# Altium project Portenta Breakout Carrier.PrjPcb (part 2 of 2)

## Sheet HDConn_MALE.SchDoc: Portenta Breakout Carrier
size A3; Author: S. Navaretti; DocumentNumber: ASX00031; Revision: V1.3; SheetNumber: 6; SheetTotal: 6; RevAuthor: Silvio Navaretti
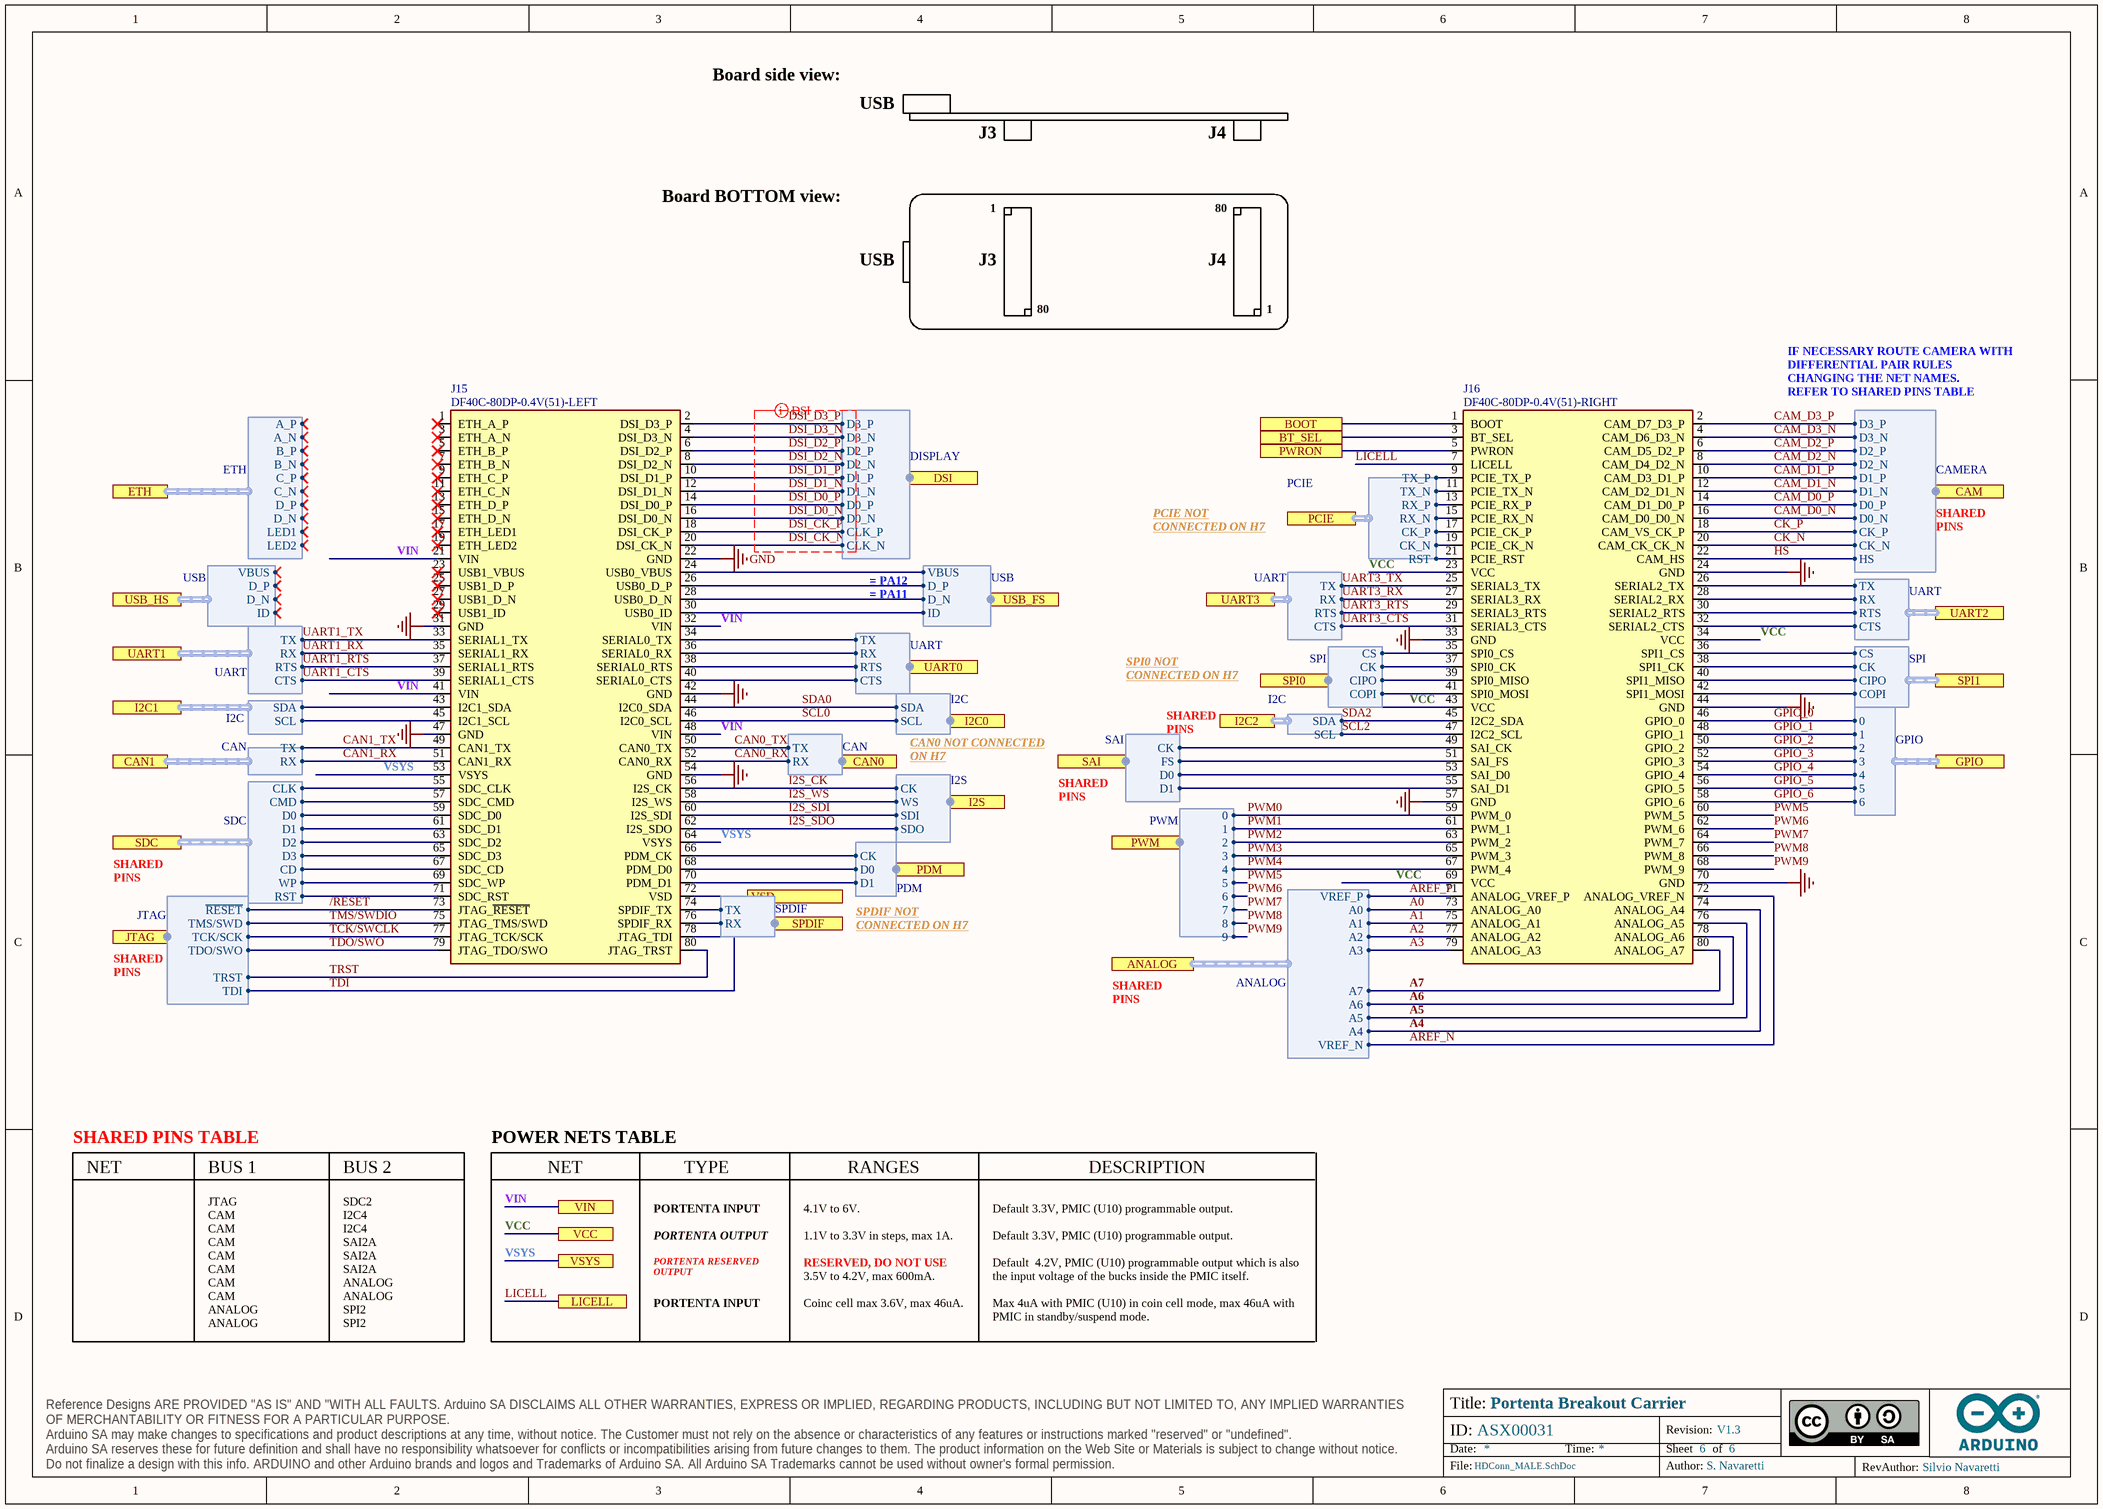
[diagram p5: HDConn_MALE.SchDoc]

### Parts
J15  DF40C-80DP-0.4V(51)-LEFT  [DF40C-80DP-0.4V(51)-Footprint-1]
J16  DF40C-80DP-0.4V(51)-RIGHT  [DF40C-80DP-0.4V(51)-Footprint-1]

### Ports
ANALOG (harness ANALOG), BOOT, BT_SEL, CAM (harness CAMERA), CAN0 (harness CAN), CAN1 (harness CAN), DSI (harness DISPLAY), ETH (harness ETH), GPIO (harness GPIO), I2C0 (harness I2C), I2C1 (harness I2C), I2C2 (harness I2C), I2S (harness I2S), JTAG (harness JTAG), LICELL, PCIE (harness PCIE), PDM (harness PDM), PWM (harness PWM), PWRON, SAI (harness SAI), SDC (harness SDC), SPDIF (harness SPDIF), SPI0 (harness SPI), SPI1 (harness SPI), UART0 (harness UART), UART1 (harness UART), UART2 (harness UART), UART3 (harness UART), USB_FS (harness USB), USB_HS (harness USB), VCC, VIN, VSD, VSYS

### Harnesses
ANALOG: VREF_P, A0, A1, A2, A3, A7, A6, A5, A4, VREF_N
PWM: 0, 1, 2, 3, 4, 5, 6, 7, 8, 9
GPIO: 0, 1, 2, 3, 4, 5, 6
ETH: A_P, A_N, B_P, B_N, C_P, C_N, D_P, D_N, LED1, LED2
USB: VBUS, D_P, D_N, ID
UART: RX, TX, RTS, CTS
I2C: SCL, SDA
CAN: RX, TX
SDC: CLK, CMD, D0, D1, D2, D3, CD, WP, RST
JTAG: ~{RESET}, TCK/SCK, TDI, TDO/SWO, TMS/SWD, TRST
DISPLAY: CLK_N, CLK_P, D0_N, D0_P, D1_N, D1_P, D2_N, D2_P, D3_N, D3_P
I2C: SDA, SCL
I2S: CK, SDI, SDO, WS
PDM: CK, D0, D1
SAI: CK, FS, D0, D1
SPI: CS, CK, CIPO, COPI
PCIE: TX_P, TX_N, RX_P, RX_N, CK_P, CK_N, RST
SPDIF: RX, TX
CAMERA: D3_P, D3_N, D2_P, D2_N, D1_P, D1_N, D0_P, D0_N, CK_P, CK_N, HS

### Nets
GND: J15.22(GND) J15.31(GND) J15.42(GND) J15.47(GND) J15.54(GND) J16.24(GND) J16.33(GND) J16.44(GND) J16.57(GND) J16.70(GND)
VCC: J16.23(VCC) J16.34(VCC) J16.43(VCC) J16.69(VCC) ; port VCC  [project net +3V3]
VIN: J15.21(VIN) J15.32(VIN) J15.41(VIN) J15.48(VIN) ; port VIN  [project net +5V]
VSD: J15.72(VSD) ; port VSD
/RESET: J15.73(JTAG_~{RESET}) ; port JTAG.~{RESET}  [project net JTAG.~{RESET}]
A0: J16.73(ANALOG_A0) ; port ANALOG.A0
A1: J16.75(ANALOG_A1) ; port ANALOG.A1
A2: J16.77(ANALOG_A2) ; port ANALOG.A2
A3: J16.79(ANALOG_A3) ; port ANALOG.A3
A4: J16.74(ANALOG_A4) ; port ANALOG.A4
A5: J16.76(ANALOG_A5) ; port ANALOG.A5
A6: J16.78(ANALOG_A6) ; port ANALOG.A6
A7: J16.80(ANALOG_A7) ; port ANALOG.A7
AREF_N: J16.72(ANALOG_VREF_N) ; port ANALOG.VREF_N  [project net ANALOG.VREF_N]
AREF_P: J16.71(ANALOG_VREF_P) ; port ANALOG.VREF_P  [project net ANALOG.VREF_P]
BOOT: J16.1(BOOT) ; port BOOT
BT_SEL: J16.3(BT_SEL) ; port BT_SEL
CAM_D0_N: J16.16(CAM_D0_D0_N) ; port CAM.D0_N  [project net CAM.D0_N]
CAM_D0_P: J16.14(CAM_D1_D0_P) ; port CAM.D0_P  [project net CAM.D0_P]
CAM_D1_N: J16.12(CAM_D2_D1_N) ; port CAM.D1_N  [project net CAM.D1_N]
CAM_D1_P: J16.10(CAM_D3_D1_P) ; port CAM.D1_P  [project net CAM.D1_P]
CAM_D2_N: J16.8(CAM_D4_D2_N) ; port CAM.D2_N  [project net CAM.D2_N]
CAM_D2_P: J16.6(CAM_D5_D2_P) ; port CAM.D2_P  [project net CAM.D2_P]
CAM_D3_N: J16.4(CAM_D6_D3_N) ; port CAM.D3_N  [project net CAM.D3_N]
CAM_D3_P: J16.2(CAM_D7_D3_P) ; port CAM.D3_P  [project net CAM.D3_P]
CAN0_RX: J15.52(CAN0_RX) ; port CAN0.RX  [project net CAN0.RX]
CAN0_TX: J15.50(CAN0_TX) ; port CAN0.TX  [project net CAN0.TX]
CAN1_RX: J15.51(CAN1_RX) ; port CAN1.RX  [project net CAN1.RX]
CAN1_TX: J15.49(CAN1_TX) ; port CAN1.TX  [project net CAN1.TX]
CIPO_OMV: J16.40(SPI1_MISO) ; port SPI1.CIPO
CK_N: J16.20(CAM_CK_CK_N) ; port CAM.CK_N  [project net CAM.CK_N]
CK_OMV: J16.38(SPI1_CK) ; port SPI1.CK
CK_P: J16.18(CAM_VS_CK_P) ; port CAM.CK_P  [project net CAM.CK_P]
COPI_OMV: J16.42(SPI1_MOSI) ; port SPI1.COPI
DSI_CK_N: J15.20(DSI_CK_N) ; port DSI.CLK_N  [project net DISPLAY.CLK_N]
DSI_CK_P: J15.18(DSI_CK_P) ; port DSI.CLK_P  [project net DISPLAY.CLK_P]
DSI_D0_N: J15.16(DSI_D0_N) ; port DSI.D0_N  [project net DISPLAY.D0_N]
DSI_D0_P: J15.14(DSI_D0_P) ; port DSI.D0_P  [project net DISPLAY.D0_P]
DSI_D1_N: J15.12(DSI_D1_N) ; port DSI.D1_N  [project net DISPLAY.D1_N]
DSI_D1_P: J15.10(DSI_D1_P) ; port DSI.D1_P  [project net DISPLAY.D1_P]
DSI_D2_N: J15.8(DSI_D2_N) ; port DSI.D2_N  [project net DISPLAY.D2_N]
DSI_D2_P: J15.6(DSI_D2_P) ; port DSI.D2_P  [project net DISPLAY.D2_P]
DSI_D3_N: J15.4(DSI_D3_N) ; port DSI.D3_N  [project net DISPLAY.D3_N]
DSI_D3_P: J15.2(DSI_D3_P) ; port DSI.D3_P  [project net DISPLAY.D3_P]
GPIO_0: J16.46(GPIO_0) ; port GPIO.0  [project net GPIO.0]
GPIO_1: J16.48(GPIO_1) ; port GPIO.1  [project net GPIO.1]
GPIO_2: J16.50(GPIO_2) ; port GPIO.2  [project net GPIO.2]
GPIO_3: J16.52(GPIO_3) ; port GPIO.3  [project net GPIO.3]
GPIO_4: J16.54(GPIO_4) ; port GPIO.4  [project net GPIO.4]
GPIO_5: J16.56(GPIO_5) ; port GPIO.5  [project net GPIO.5]
GPIO_6: J16.58(GPIO_6) ; port GPIO.6  [project net GPIO.6]
HS: J16.22(CAM_HS) ; port CAM.HS  [project net CAM.HS]
I2C1.SCL: J15.45(I2C1_SCL) ; port I2C1.SCL
I2C1.SDA: J15.43(I2C1_SDA) ; port I2C1.SDA
I2S_CK: J15.56(I2S_CK) ; port I2S.CK  [project net I2S.CK]
I2S_SDI: J15.60(I2S_SDI) ; port I2S.SDI  [project net I2S.SDI]
I2S_SDO: J15.62(I2S_SDO) ; port I2S.SDO  [project net I2S.SDO]
I2S_WS: J15.58(I2S_WS) ; port I2S.WS  [project net I2S.WS]
LICELL: J16.7(LICELL) ; port LICELL
PCIE.CK_N: J16.19(PCIE_CK_N) ; port PCIE.CK_N
PCIE.CK_P: J16.17(PCIE_CK_P) ; port PCIE.CK_P
PCIE.RST: J16.21(PCIE_RST) ; port PCIE.RST
PCIE.RX_N: J16.15(PCIE_RX_N) ; port PCIE.RX_N
PCIE.RX_P: J16.13(PCIE_RX_P) ; port PCIE.RX_P
PCIE.TX_N: J16.11(PCIE_TX_N) ; port PCIE.TX_N
PCIE.TX_P: J16.9(PCIE_TX_P) ; port PCIE.TX_P
PDM.CK: J15.66(PDM_CK) ; port PDM.CK
PDM.D0: J15.68(PDM_D0) ; port PDM.D0
PDM.D1: J15.70(PDM_D1) ; port PDM.D1
PWM0: J16.59(PWM_0) ; port PWM.0  [project net PWM.0]
PWM1: J16.61(PWM_1) ; port PWM.1  [project net PWM.1]
PWM2: J16.63(PWM_2) ; port PWM.2  [project net PWM.2]
PWM3: J16.65(PWM_3) ; port PWM.3  [project net PWM.3]
PWM4: J16.67(PWM_4) ; port PWM.4  [project net PWM.4]
PWM5: J16.60(PWM_5) ; port PWM.5  [project net PWM.5]
PWM6: J16.62(PWM_6) ; port PWM.6  [project net PWM.6]
PWM7: J16.64(PWM_7) ; port PWM.7  [project net PWM.7]
PWM8: J16.66(PWM_8) ; port PWM.8  [project net PWM.8]
PWM9: J16.68(PWM_9) ; port PWM.9  [project net PWM.9]
PWRON: J16.5(PWRON) ; port PWRON
SAI.CK: J16.49(SAI_CK) ; port SAI.CK
SAI.D0: J16.53(SAI_D0) ; port SAI.D0
SAI.D1: J16.55(SAI_D1) ; port SAI.D1
SAI.FS: J16.51(SAI_FS) ; port SAI.FS
SCL0: J15.46(I2C0_SCL) ; port I2C0.SCL  [project net I2C0.SCL]
SCL2: J16.47(I2C2_SCL) ; port I2C2.SCL  [project net I2C2.SCL]
SDA0: J15.44(I2C0_SDA) ; port I2C0.SDA  [project net I2C0.SDA]
SDA2: J16.45(I2C2_SDA) ; port I2C2.SDA  [project net I2C2.SDA]
SDC.CD: J15.67(SDC_CD) ; port SDC.CD
SDC.CLK: J15.55(SDC_CLK) ; port SDC.CLK
SDC.CMD: J15.57(SDC_CMD) ; port SDC.CMD
SDC.D0: J15.59(SDC_D0) ; port SDC.D0
SDC.D1: J15.61(SDC_D1) ; port SDC.D1
SDC.D2: J15.63(SDC_D2) ; port SDC.D2
SDC.D3: J15.65(SDC_D3) ; port SDC.D3
SDC.RST: J15.71(SDC_RST) ; port SDC.RST
SDC.WP: J15.69(SDC_WP) ; port SDC.WP
SPDIF.RX: J15.76(SPDIF_RX) ; port SPDIF.RX
SPDIF.TX: J15.74(SPDIF_TX) ; port SPDIF.TX
SPI0.CIPO: J16.39(SPI0_MISO) ; port SPI0.CIPO
SPI0.CK: J16.37(SPI0_CK) ; port SPI0.CK
SPI0.COPI: J16.41(SPI0_MOSI) ; port SPI0.COPI
SPI0.CS: J16.35(SPI0_CS) ; port SPI0.CS
SPI1.CS: J16.36(SPI1_CS) ; port SPI1.CS
TCK/SWCLK: J15.77(JTAG_TCK/SCK) ; port JTAG.TCK/SCK  [project net JTAG.TCK/SCK]
TDI: J15.78(JTAG_TDI) ; port JTAG.TDI  [project net JTAG.TDI]
TDO/SWO: J15.79(JTAG_TDO/SWO) ; port JTAG.TDO/SWO  [project net JTAG.TDO/SWO]
TMS/SWDIO: J15.75(JTAG_TMS/SWD) ; port JTAG.TMS/SWD  [project net JTAG.TMS/SWD]
TRST: J15.80(JTAG_TRST) ; port JTAG.TRST  [project net JTAG.TRST]
UART0.CTS: J15.40(SERIAL0_CTS) ; port UART0.CTS
UART0.RTS: J15.38(SERIAL0_RTS) ; port UART0.RTS
UART0.RX: J15.36(SERIAL0_RX) ; port UART0.RX
UART0.TX: J15.34(SERIAL0_TX) ; port UART0.TX
UART1_CTS: J15.39(SERIAL1_CTS) ; port UART1.CTS  [project net UART1.CTS]
UART1_RTS: J15.37(SERIAL1_RTS) ; port UART1.RTS  [project net UART1.RTS]
UART1_RX: J15.35(SERIAL1_RX) ; port UART1.RX  [project net UART1.RX]
UART1_TX: J15.33(SERIAL1_TX) ; port UART1.TX  [project net UART1.TX]
UART2.CTS: J16.32(SERIAL2_CTS) ; port UART2.CTS
UART2.RTS: J16.30(SERIAL2_RTS) ; port UART2.RTS
UART2.RX: J16.28(SERIAL2_RX) ; port UART2.RX
UART2.TX: J16.26(SERIAL2_TX) ; port UART2.TX
UART3_CTS: J16.31(SERIAL3_CTS) ; port UART3.CTS  [project net UART3.CTS]
UART3_RTS: J16.29(SERIAL3_RTS) ; port UART3.RTS  [project net UART3.RTS]
UART3_RX: J16.27(SERIAL3_RX) ; port UART3.RX  [project net UART3.RX]
UART3_TX: J16.25(SERIAL3_TX) ; port UART3.TX  [project net UART3.TX]
VSYS: J15.53(VSYS) J15.64(VSYS) ; port VSYS
NetJ15_24: J15.24(USB0_VBUS) ; port USB_FS.VBUS
NetJ15_26: J15.26(USB0_D_P) ; port USB_FS.D_P
NetJ15_28: J15.28(USB0_D_N) ; port USB_FS.D_N
NetJ15_30: J15.30(USB0_ID) ; port USB_FS.ID

Not connected (* = marked no-connect by the designer): J15 1(ETH_A_P)* 3(ETH_A_N)* 5(ETH_B_P)* 7(ETH_B_N)* 9(ETH_C_P)* 11(ETH_C_N)* 13(ETH_D_P)* 15(ETH_D_N)* 17(ETH_LED1)* 19(ETH_LED2)* 23(USB1_VBUS)* 25(USB1_D_P)* 27(USB1_D_N)* 29(USB1_ID)*

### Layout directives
differential pair; differential pair class DSI: DSI_CK_N, DSI_CK_P, DSI_D0_N, DSI_D0_P, DSI_D1_N, DSI_D1_P, DSI_D2_N, DSI_D2_P, DSI_D3_N, DSI_D3_P

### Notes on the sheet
- Board side view:
- USB
- J3
- J4
- Board BOTTOM view:
- 1
- 80
- IF NECESSARY ROUTE CAMERA WITH DIFFERENTIAL PAIR RULES CHANGING THE NET NAMES.
  REFER TO SHARED PINS TABLE
- PCIE NOT CONNECTED ON H7
- SHARED PINS
- SPI0 NOT CONNECTED ON H7
- CAN0 NOT CONNECTED ON H7
- SPDIF NOT CONNECTED ON H7
- SHARED PINS TABLE
- NET
- BUS 1
- BUS 2
- POWER NETS TABLE
- TYPE
- RANGES
- DESCRIPTION
- JTAG
- CAM
- SDC2
- I2C4
- SAI2A
- PORTENTA INPUT
- PORTENTA OUTPUT
- 4.1V to 6V.
- 1.1V to 3.3V in steps, max 1A.
- RESERVED, DO NOT USE
- Default 3.3V, PMIC (U10) programmable output.
- ANALOG
- SPI2
- PORTENTA RESERVED OUTPUT
- Coinc cell max 3.6V, max 46uA.
- 3.5V to 4.2V, max 600mA.
- Default  4.2V, PMIC (U10) programmable output which is also the input voltage of the bucks inside the PMIC itself.
- Max 4uA with PMIC (U10) in coin cell mode, max 46uA with PMIC in standby/suspend mode.

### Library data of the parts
J15 = J0015-A.8: CONN HDR 80POS 0.4MM MALE SMD GOLD; Manufacturer: Hirose; Code Arduino: J0015; Connector Type: Plug
J16 = J0152-A.3: CONN HDR 80POS 0.4MM MALE SMD GOLD; Manufacturer: Hirose; Code Arduino: J0015; Connector Type: Plug

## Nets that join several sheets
+3V3: TOP (21 pins), HDConn_FEMALE (J2.23 J2.34 J2.43 J2.69), ETHERNET (R19.2 SJ1.2 SJ2.2), USB (R22.1), HDConn_MALE (J16.23 J16.34 J16.43 J16.69)
+5V: TOP (CAN0.1 CAN1.1 J8.1), HDConn_FEMALE (J1.21 J1.32 J1.41 J1.48), USB (U1.2 U1.3), HDConn_MALE (J15.21 J15.32 J15.41 J15.48)
GND: TOP (39 pins), HDConn_FEMALE (10 pins), ETHERNET (C21.2 C81.2 J7.S3 R18.2), USB (9 pins), SD_CONNECTOR (7 pins), HDConn_MALE (10 pins)
VSD: TOP (SDCARD.1), HDConn_FEMALE (J1.72), SD_CONNECTOR (R1.1), HDConn_MALE (J15.72)
A0: TOP (ANALOG.8), HDConn_FEMALE (J2.73), HDConn_MALE (J16.73)
A1: TOP (ANALOG.7), HDConn_FEMALE (J2.75), HDConn_MALE (J16.75)
A2: TOP (ANALOG.6), HDConn_FEMALE (J2.77), HDConn_MALE (J16.77)
A3: TOP (ANALOG.5), HDConn_FEMALE (J2.79), HDConn_MALE (J16.79)
A4: TOP (ANALOG.4), HDConn_FEMALE (J2.74), HDConn_MALE (J16.74)
A5: TOP (ANALOG.3), HDConn_FEMALE (J2.76), HDConn_MALE (J16.76)
A6: TOP (ANALOG.2), HDConn_FEMALE (J2.78), HDConn_MALE (J16.78)
A7: TOP (ANALOG.1), HDConn_FEMALE (J2.80), HDConn_MALE (J16.80)
ANALOG.VREF_N: TOP (ANALOG.10), HDConn_FEMALE (J2.72), HDConn_MALE (J16.72)
ANALOG.VREF_P: TOP (ANALOG.9), HDConn_FEMALE (J2.71), HDConn_MALE (J16.71)
BOOT: TOP (SW1.3), HDConn_FEMALE (J2.1), HDConn_MALE (J16.1)
BT_SEL: TOP (SW1.4), HDConn_FEMALE (J2.3), HDConn_MALE (J16.3)
CAM.CK_N: TOP (CAMERA.3 J4.14), HDConn_FEMALE (J2.20), HDConn_MALE (J16.20)
CAM.CK_P: TOP (CAMERA.4 J4.16), HDConn_FEMALE (J2.18), HDConn_MALE (J16.18)
CAM.D0_N: TOP (CAMERA.11 J4.31), HDConn_FEMALE (J2.16), HDConn_MALE (J16.16)
CAM.D0_P: TOP (CAMERA.12 J4.29), HDConn_FEMALE (J2.14), HDConn_MALE (J16.14)
CAM.D1_N: TOP (CAMERA.9 J4.35), HDConn_FEMALE (J2.12), HDConn_MALE (J16.12)
CAM.D1_P: TOP (CAMERA.10 J4.28), HDConn_FEMALE (J2.10), HDConn_MALE (J16.10)
CAM.D2_N: TOP (CAMERA.7 J4.26), HDConn_FEMALE (J2.8), HDConn_MALE (J16.8)
CAM.D2_P: TOP (CAMERA.8 J4.33), HDConn_FEMALE (J2.6), HDConn_MALE (J16.6)
CAM.D3_N: TOP (CAMERA.5 J4.24), HDConn_FEMALE (J2.4), HDConn_MALE (J16.4)
CAM.D3_P: TOP (CAMERA.6 J4.22), HDConn_FEMALE (J2.2), HDConn_MALE (J16.2)
CAM.HS: TOP (CAMERA.2 J4.18), HDConn_FEMALE (J2.22), HDConn_MALE (J16.22)
CAN0.RX: TOP (CAN0.3), HDConn_FEMALE (J1.52), HDConn_MALE (J15.52)
CAN0.TX: TOP (CAN0.2), HDConn_FEMALE (J1.50), HDConn_MALE (J15.50)
CAN1.RX: TOP (CAN1.3), HDConn_FEMALE (J1.51), HDConn_MALE (J15.51)
CAN1.TX: TOP (CAN1.2), HDConn_FEMALE (J1.49), HDConn_MALE (J15.49)
CIPO_OMV: TOP (J4.15 SPI1.4), HDConn_FEMALE (J2.40), HDConn_MALE (J16.40)
CK_OMV: TOP (J4.13 SPI1.3), HDConn_FEMALE (J2.38), HDConn_MALE (J16.38)
COPI_OMV: TOP (J4.17 SPI1.5), HDConn_FEMALE (J2.42), HDConn_MALE (J16.42)
DISPLAY.CLK_N: TOP (DISPLAY.10), HDConn_FEMALE (J1.20), HDConn_MALE (J15.20)
DISPLAY.CLK_P: TOP (DISPLAY.9), HDConn_FEMALE (J1.18), HDConn_MALE (J15.18)
DISPLAY.D0_N: TOP (DISPLAY.8), HDConn_FEMALE (J1.16), HDConn_MALE (J15.16)
DISPLAY.D0_P: TOP (DISPLAY.7), HDConn_FEMALE (J1.14), HDConn_MALE (J15.14)
DISPLAY.D1_N: TOP (DISPLAY.6), HDConn_FEMALE (J1.12), HDConn_MALE (J15.12)
DISPLAY.D1_P: TOP (DISPLAY.5), HDConn_FEMALE (J1.10), HDConn_MALE (J15.10)
DISPLAY.D2_N: TOP (DISPLAY.4), HDConn_FEMALE (J1.8), HDConn_MALE (J15.8)
DISPLAY.D2_P: TOP (DISPLAY.3), HDConn_FEMALE (J1.6), HDConn_MALE (J15.6)
DISPLAY.D3_N: TOP (DISPLAY.2), HDConn_FEMALE (J1.4), HDConn_MALE (J15.4)
DISPLAY.D3_P: TOP (DISPLAY.1), HDConn_FEMALE (J1.2), HDConn_MALE (J15.2)
ETH.A_N: TOP (ETHERNET.3), HDConn_FEMALE (J1.3), ETHERNET (J7.P2)
ETH.A_P: TOP (ETHERNET.1), HDConn_FEMALE (J1.1), ETHERNET (J7.P1)
ETH.B_N: TOP (ETHERNET.7), HDConn_FEMALE (J1.7), ETHERNET (J7.P4)
ETH.B_P: TOP (ETHERNET.5), HDConn_FEMALE (J1.5), ETHERNET (J7.P3)
ETH.C_N: TOP (ETHERNET.11), HDConn_FEMALE (J1.11), ETHERNET (J7.P8)
ETH.C_P: TOP (ETHERNET.9), HDConn_FEMALE (J1.9), ETHERNET (J7.P7)
ETH.D_N: TOP (ETHERNET.10), HDConn_FEMALE (J1.15), ETHERNET (J7.P10)
ETH.D_P: TOP (ETHERNET.12), HDConn_FEMALE (J1.13), ETHERNET (J7.P9)
ETH.LED1: TOP (ETHERNET.2), HDConn_FEMALE (J1.17), ETHERNET (J7.L1)
ETH.LED2: TOP (ETHERNET.4), HDConn_FEMALE (J1.19), ETHERNET (J7.L4)
GPIO.0: TOP (GPIO.2 R14.2), HDConn_FEMALE (J2.46), HDConn_MALE (J16.46)
GPIO.1: TOP (GPIO.3 R15.2), HDConn_FEMALE (J2.48), HDConn_MALE (J16.48)
GPIO.2: TOP (GPIO.4 J12.3), HDConn_FEMALE (J2.50), HDConn_MALE (J16.50)
GPIO.3: TOP (GPIO.5 R16.2), HDConn_FEMALE (J2.52), HDConn_MALE (J16.52)
GPIO.4: TOP (GPIO.6 J12.8), HDConn_FEMALE (J2.54), HDConn_MALE (J16.54)
GPIO.5: TOP (GPIO.7 J12.1), HDConn_FEMALE (J2.56), HDConn_MALE (J16.56)
GPIO.6: TOP (GPIO.8), HDConn_FEMALE (J2.58), HDConn_MALE (J16.58)
I2C0.SCL: TOP (I2C.4), HDConn_FEMALE (J1.46), HDConn_MALE (J15.46)
I2C0.SDA: TOP (I2C.3), HDConn_FEMALE (J1.44), HDConn_MALE (J15.44)
I2C1.SCL: TOP (I2C.8), HDConn_FEMALE (J1.45), HDConn_MALE (J15.45)
I2C1.SDA: TOP (I2C.7), HDConn_FEMALE (J1.43), HDConn_MALE (J15.43)
I2C2.SCL: TOP (I2C.12 J4.32), HDConn_FEMALE (J2.47), HDConn_MALE (J16.47)
I2C2.SDA: TOP (I2C.11 J4.34), HDConn_FEMALE (J2.45), HDConn_MALE (J16.45)
I2S.CK: TOP (I2S.2), HDConn_FEMALE (J1.56), HDConn_MALE (J15.56)
I2S.SDI: TOP (I2S.4), HDConn_FEMALE (J1.60), HDConn_MALE (J15.60)
I2S.SDO: TOP (I2S.5), HDConn_FEMALE (J1.62), HDConn_MALE (J15.62)
I2S.WS: TOP (I2S.3), HDConn_FEMALE (J1.58), HDConn_MALE (J15.58)
JTAG.~{RESET}: TOP (JTAG.10), HDConn_FEMALE (J1.73), HDConn_MALE (J15.73)
JTAG.TCK/SCK: TOP (JTAG.4), HDConn_FEMALE (J1.77), HDConn_MALE (J15.77)
JTAG.TDI: TOP (JTAG.8), HDConn_FEMALE (J1.78), HDConn_MALE (J15.78)
JTAG.TDO/SWO: TOP (JTAG.6), HDConn_FEMALE (J1.79), HDConn_MALE (J15.79)
JTAG.TMS/SWD: TOP (JTAG.2), HDConn_FEMALE (J1.75), HDConn_MALE (J15.75)
JTAG.TRST: TOP (J11.1), HDConn_FEMALE (J1.80), HDConn_MALE (J15.80)
LICELL: TOP (J6.1 J6.2), HDConn_FEMALE (J2.7), HDConn_MALE (J16.7)
PCIE.CK_N: TOP (PCIE2.3), HDConn_FEMALE (J2.19), HDConn_MALE (J16.19)
PCIE.CK_P: TOP (PCIE1.3), HDConn_FEMALE (J2.17), HDConn_MALE (J16.17)
PCIE.RST: TOP (PCIE1.4), HDConn_FEMALE (J2.21), HDConn_MALE (J16.21)
PCIE.RX_N: TOP (PCIE2.2), HDConn_FEMALE (J2.15), HDConn_MALE (J16.15)
PCIE.RX_P: TOP (PCIE1.2), HDConn_FEMALE (J2.13), HDConn_MALE (J16.13)
PCIE.TX_N: TOP (PCIE2.1), HDConn_FEMALE (J2.11), HDConn_MALE (J16.11)
PCIE.TX_P: TOP (PCIE1.1), HDConn_FEMALE (J2.9), HDConn_MALE (J16.9)
PDM.CK: TOP (J12.6 PDM.1), HDConn_FEMALE (J1.66), HDConn_MALE (J15.66)
PDM.D0: TOP (PDM.3), HDConn_FEMALE (J1.68), HDConn_MALE (J15.68)
PDM.D1: TOP (PDM.2), HDConn_FEMALE (J1.70), HDConn_MALE (J15.70)
PWM.0: TOP (J4.12 PWM.10), HDConn_FEMALE (J2.59), HDConn_MALE (J16.59)
PWM.1: TOP (PWM.9), HDConn_FEMALE (J2.61), HDConn_MALE (J16.61)
PWM.2: TOP (PWM.8), HDConn_FEMALE (J2.63), HDConn_MALE (J16.63)
PWM.3: TOP (PWM.7), HDConn_FEMALE (J2.65), HDConn_MALE (J16.65)
PWM.4: TOP (PWM.6), HDConn_FEMALE (J2.67), HDConn_MALE (J16.67)
PWM.5: TOP (PWM.5), HDConn_FEMALE (J2.60), HDConn_MALE (J16.60)
PWM.6: TOP (PWM.4), HDConn_FEMALE (J2.62), HDConn_MALE (J16.62)
PWM.7: TOP (PWM.3), HDConn_FEMALE (J2.64), HDConn_MALE (J16.64)
PWM.8: TOP (PWM.2), HDConn_FEMALE (J2.66), HDConn_MALE (J16.66)
PWM.9: TOP (PWM.1), HDConn_FEMALE (J2.68), HDConn_MALE (J16.68)
PWRON: TOP (PB1.6), HDConn_FEMALE (J2.5), HDConn_MALE (J16.5)
SAI.CK: TOP (SAI.2), HDConn_FEMALE (J2.49), HDConn_MALE (J16.49)
SAI.D0: TOP (SAI.5), HDConn_FEMALE (J2.53), HDConn_MALE (J16.53)
SAI.D1: TOP (SAI.4), HDConn_FEMALE (J2.55), HDConn_MALE (J16.55)
SAI.FS: TOP (SAI.3), HDConn_FEMALE (J2.51), HDConn_MALE (J16.51)
SDC.CD: TOP (SDCARD.8), HDConn_FEMALE (J1.67), SD_CONNECTOR (J5.CD1), HDConn_MALE (J15.67)
SDC.CLK: TOP (SDCARD.3), HDConn_FEMALE (J1.55), SD_CONNECTOR (J5.5), HDConn_MALE (J15.55)
SDC.CMD: TOP (SDCARD.5), HDConn_FEMALE (J1.57), SD_CONNECTOR (J5.3), HDConn_MALE (J15.57)
SDC.D0: TOP (SDCARD.7), HDConn_FEMALE (J1.59), SD_CONNECTOR (J5.7), HDConn_MALE (J15.59)
SDC.D1: TOP (SDCARD.2), HDConn_FEMALE (J1.61), SD_CONNECTOR (J5.8), HDConn_MALE (J15.61)
SDC.D2: TOP (SDCARD.4), HDConn_FEMALE (J1.63), SD_CONNECTOR (J5.1), HDConn_MALE (J15.63)
SDC.D3: TOP (SDCARD.6), HDConn_FEMALE (J1.65), SD_CONNECTOR (J5.2), HDConn_MALE (J15.65)
SDC.RST: TOP (SDCARD.12), HDConn_FEMALE (J1.71), HDConn_MALE (J15.71)
SDC.WP: TOP (SDCARD.10), HDConn_FEMALE (J1.69), HDConn_MALE (J15.69)
SPDIF.RX: TOP (SPDIF.2), HDConn_FEMALE (J1.76), HDConn_MALE (J15.76)
SPDIF.TX: TOP (SPDIF.1), HDConn_FEMALE (J1.74), HDConn_MALE (J15.74)
SPI0.CIPO: TOP (SPI0.4), HDConn_FEMALE (J2.39), HDConn_MALE (J16.39)
SPI0.CK: TOP (SPI0.3), HDConn_FEMALE (J2.37), HDConn_MALE (J16.37)
SPI0.COPI: TOP (SPI0.5), HDConn_FEMALE (J2.41), HDConn_MALE (J16.41)
SPI0.CS: TOP (SPI0.2), HDConn_FEMALE (J2.35), HDConn_MALE (J16.35)
SPI1.CS: TOP (R17.2 SPI1.2), HDConn_FEMALE (J2.36), HDConn_MALE (J16.36)
~{USBA_VBUS_EN}: TOP (J12.2), USB (R4.1 U1.4)
~{USBA_VBUS_FLAG}: TOP (J12.4), USB (R22.2 U1.10)
UART0.CTS: TOP (UART0.5), HDConn_FEMALE (J1.40), HDConn_MALE (J15.40)
UART0.RTS: TOP (UART0.4), HDConn_FEMALE (J1.38), HDConn_MALE (J15.38)
UART0.RX: TOP (UART0.3), HDConn_FEMALE (J1.36), HDConn_MALE (J15.36)
UART0.TX: TOP (UART0.2), HDConn_FEMALE (J1.34), HDConn_MALE (J15.34)
UART1.CTS: TOP (UART1.5), HDConn_FEMALE (J1.39), HDConn_MALE (J15.39)
UART1.RTS: TOP (UART1.4), HDConn_FEMALE (J1.37), HDConn_MALE (J15.37)
UART1.RX: TOP (UART1.3), HDConn_FEMALE (J1.35), HDConn_MALE (J15.35)
UART1.TX: TOP (UART1.2), HDConn_FEMALE (J1.33), HDConn_MALE (J15.33)
UART2.CTS: TOP (UART2.5), HDConn_FEMALE (J2.32), HDConn_MALE (J16.32)
UART2.RTS: TOP (UART2.4), HDConn_FEMALE (J2.30), HDConn_MALE (J16.30)
UART2.RX: TOP (UART2.3), HDConn_FEMALE (J2.28), HDConn_MALE (J16.28)
UART2.TX: TOP (J11.3 UART2.2), HDConn_FEMALE (J2.26), HDConn_MALE (J16.26)
UART3.CTS: TOP (UART3.5), HDConn_FEMALE (J2.31), HDConn_MALE (J16.31)
UART3.RTS: TOP (UART3.4), HDConn_FEMALE (J2.29), HDConn_MALE (J16.29)
UART3.RX: TOP (UART3.3), HDConn_FEMALE (J2.27), HDConn_MALE (J16.27)
UART3.TX: TOP (UART3.2), HDConn_FEMALE (J2.25), HDConn_MALE (J16.25)
USB_FS.D_N: TOP (USBFS.3), HDConn_FEMALE (J1.28), USB (D1.3 J3.2)
USB_FS.D_P: TOP (USBFS.2), HDConn_FEMALE (J1.26), USB (D1.2 J3.3)
USB_FS.ID: TOP (USBFS.4), HDConn_FEMALE (J1.30)
USB_FS.VBUS: TOP (USBFS.1), HDConn_FEMALE (J1.24), USB (C3.1 D1.4 J3.1 U1.9)
USB_HS.D_N: TOP (R7.2), HDConn_FEMALE (J1.27)
USB_HS.D_P: TOP (R6.2), HDConn_FEMALE (J1.25)
USB_HS.ID: TOP (R8.2), HDConn_FEMALE (J1.29)
USB_HS.VBUS: TOP (USBHS.1), HDConn_FEMALE (J1.23)
VSYS: TOP (TP1.X), HDConn_FEMALE (J1.53 J1.64), HDConn_MALE (J15.53 J15.64)

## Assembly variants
SL-ASX00031: not fitted ANALOG CAMERA CAN0 CAN1 DISPLAY ETHERNET GPIO I2C I2S PCIE1 PCIE2 PDM PortentaBoardShape_3D_Hirose3.5mm PWM R6 R7 R8 SAI SDCARD SPDIF SPI0 SPI1 UART0 UART1 UART2 UART3 USBFS USBHS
